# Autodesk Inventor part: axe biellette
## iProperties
Created: 2002-04
Part Number: axe biellette
Material: Par défaut
Document SubType Name: Modélisation
Designer: thchene
Control State: 0
Master: False
Checked Out: False
Shininess: 20.0
Angle Display Precision: 2
Document Length Units: 11269
Document Angle Units: 11279
Document Time Units: 11290
Document Mass Units: 11283
Document Length Units Precision: 3
Document Angle Units Precision: 2
Compacted: True
Density: 0.0
Volumn: 0.0
Area: 0.0
PropertySet Name: Model Information
Author: thchene
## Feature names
1. Révolution1 [Revolution]
2. Chanfrein1 [Chamfer]
3. Perçage2 [Hole]
